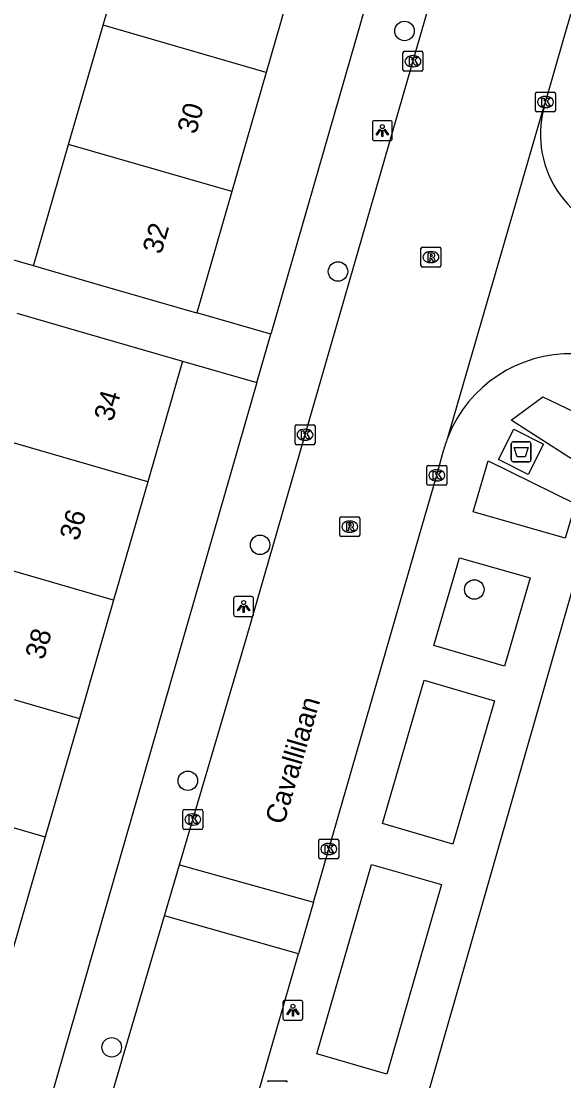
# Model space of a CAD drawing. Extents: x 159822 to 160765, y 380693 to 381634.
# Drawn here: x 160405.7 to 160432.9, y 381176.6 to 381229.8 of the extents above; entities that cross this region are included whole.
import ezdxf

# ---------------------------------------------------------------- set-up
doc = ezdxf.new("R2010")
doc.units = 0
for name, color, linetype in [('IMGEO_Afval_apart_plaats', 7, 'Continuous'), ('IMGEO_Boom', 7, 'Continuous'), ('IMGEO_Brandkraan', 7, 'Continuous'), ('IMGEO_Kolk', 7, 'Continuous'), ('IMGEO_Lichtpunt', 7, 'Continuous'), ('IMGEO_Openbare_ruimte_label', 7, 'Continuous'), ('IMGEO_Pand', 7, 'Continuous'), ('IMGEO_Pand_nummerreeks', 7, 'Continuous'), ('IMGEO_Rijbaan_lokaal_open', 7, 'Continuous'), ('IMGEO_Rioolput', 7, 'Continuous'), ('IMGEO_Voetpad_gesloten', 7, 'Continuous'), ('IMGEO_Voetpad_open', 7, 'Continuous')]:
    doc.layers.add(name, color=color, linetype=linetype)

msp = doc.modelspace()

# ---------------------------------------------------------------- linework, layer by layer
at = {"layer": 'IMGEO_Afval_apart_plaats'}
for p, q in [((160430.31, 381207.756), (160430.31, 381208.556)), ((160430.31, 381208.556), (160430.31, 381207.756)), ((160430.41, 381208.656), (160431.2, 381208.656)), ((160431.2, 381208.656), (160430.41, 381208.656)), ((160431.3, 381208.556), (160431.3, 381207.756)), ((160431.3, 381207.756), (160431.3, 381208.556)), ((160431.2, 381207.656), (160430.41, 381207.656)), ((160430.41, 381207.656), (160431.2, 381207.656))]:
    msp.add_line(p, q, dxfattribs=at)
msp.add_lwpolyline([(160430.453, 381208.37), (160431.157, 381208.37), (160431.008, 381207.9), (160430.602, 381207.9), (160430.453, 381208.37)], dxfattribs=at)
for centre, start, end in [((160430.41, 381208.556), 90, 180), ((160430.41, 381208.556), 90, 180), ((160431.2, 381208.556), 0, 90), ((160431.2, 381208.556), 360, 90), ((160430.41, 381207.756), 180, 270), ((160430.41, 381207.756), 180, 270), ((160431.2, 381207.756), 270, 0), ((160431.2, 381207.756), 270, 0)]:
    msp.add_arc(centre, 0.1, start, end, dxfattribs=at)
at = {"layer": 'IMGEO_Boom'}
for centre in [(160424.957, 381229.276), (160421.624, 381217.206), (160417.717, 381203.486), (160428.46, 381201.244), (160414.092, 381191.645), (160410.275, 381178.268)]:
    msp.add_circle(centre, 0.489, dxfattribs=at)
at = {"layer": 'IMGEO_Brandkraan'}
msp.add_line((160418.157, 381176.587), (160419.009, 381176.587), dxfattribs=at)
msp.add_lwpolyline([(160418.157, 381176.587), (160419.009, 381176.587)], dxfattribs=at)
for centre, start, end in [((160418.159, 381176.511), 91.552, 178.448), ((160418.159, 381176.511), 91.552, 178.448), ((160419.007, 381176.511), 1.552, 88.448), ((160419.007, 381176.511), 1.552, 88.448)]:
    msp.add_arc(centre, 0.0765, start, end, dxfattribs=at)
at = {"layer": 'IMGEO_Kolk'}
for p, q in [((160424.882, 381227.331), (160424.882, 381228.183)), ((160424.957, 381228.257), (160425.809, 381228.257)), ((160425.37, 381228.037), (160425.395, 381228.037)), ((160425.883, 381228.183), (160425.883, 381227.331)), ((160425.393, 381227.477), (160425.368, 381227.477)), ((160425.809, 381227.257), (160424.957, 381227.257)), ((160431.527, 381225.284), (160431.527, 381226.136)), ((160431.602, 381226.21), (160432.454, 381226.21)), ((160432.015, 381225.99), (160432.04, 381225.99)), ((160432.528, 381226.136), (160432.528, 381225.284)), ((160432.038, 381225.43), (160432.013, 381225.43)), ((160432.454, 381225.21), (160431.602, 381225.21)), ((160419.469, 381208.585), (160419.469, 381209.437)), ((160419.544, 381209.511), (160420.396, 381209.511)), ((160419.957, 381209.291), (160419.982, 381209.291)), ((160420.47, 381209.437), (160420.47, 381208.585)), ((160420.396, 381208.511), (160419.544, 381208.511)), ((160419.98, 381208.731), (160419.955, 381208.731)), ((160426.08, 381206.549), (160426.08, 381207.401)), ((160426.155, 381207.475), (160427.007, 381207.475)), ((160426.568, 381207.255), (160426.593, 381207.255)), ((160427.081, 381207.401), (160427.081, 381206.549)), ((160426.591, 381206.695), (160426.566, 381206.695)), ((160427.007, 381206.475), (160426.155, 381206.475)), ((160413.841, 381189.276), (160413.841, 381190.128)), ((160413.916, 381190.202), (160414.768, 381190.202)), ((160414.842, 381190.128), (160414.842, 381189.276)), ((160414.329, 381189.982), (160414.354, 381189.982)), ((160414.768, 381189.202), (160413.916, 381189.202)), ((160414.352, 381189.422), (160414.327, 381189.422)), ((160420.659, 381187.795), (160420.659, 381188.647)), ((160420.734, 381188.721), (160421.586, 381188.721)), ((160421.66, 381188.647), (160421.66, 381187.795)), ((160421.147, 381188.501), (160421.172, 381188.501)), ((160421.586, 381187.721), (160420.734, 381187.721)), ((160421.17, 381187.941), (160421.145, 381187.941))]:
    msp.add_line(p, q, dxfattribs=at)
for points in [[(160424.882, 381227.331), (160424.882, 381228.183)], [(160424.957, 381228.257), (160425.809, 381228.257)], [(160425.203, 381227.957), (160425.326, 381227.957), (160425.326, 381227.806), (160425.456, 381227.957), (160425.62, 381227.957), (160425.474, 381227.806), (160425.627, 381227.557), (160425.475, 381227.557), (160425.39, 381227.721), (160425.326, 381227.654), (160425.326, 381227.557), (160425.203, 381227.557), (160425.203, 381227.957)], [(160425.883, 381228.183), (160425.883, 381227.331)], [(160425.809, 381227.257), (160424.957, 381227.257)], [(160431.527, 381225.284), (160431.527, 381226.136)], [(160431.602, 381226.21), (160432.454, 381226.21)], [(160431.848, 381225.91), (160431.971, 381225.91), (160431.971, 381225.759), (160432.101, 381225.91), (160432.265, 381225.91), (160432.119, 381225.759), (160432.272, 381225.51), (160432.12, 381225.51), (160432.035, 381225.674), (160431.971, 381225.607), (160431.971, 381225.51), (160431.848, 381225.51), (160431.848, 381225.91)], [(160432.528, 381226.136), (160432.528, 381225.284)], [(160432.454, 381225.21), (160431.602, 381225.21)], [(160419.469, 381208.585), (160419.469, 381209.437)], [(160419.544, 381209.511), (160420.396, 381209.511)], [(160420.47, 381209.437), (160420.47, 381208.585)], [(160419.79, 381209.211), (160419.913, 381209.211), (160419.913, 381209.06), (160420.043, 381209.211), (160420.207, 381209.211), (160420.061, 381209.06), (160420.214, 381208.811), (160420.062, 381208.811), (160419.977, 381208.975), (160419.913, 381208.908), (160419.913, 381208.811), (160419.79, 381208.811), (160419.79, 381209.211)], [(160420.396, 381208.511), (160419.544, 381208.511)], [(160426.08, 381206.549), (160426.08, 381207.401)], [(160426.155, 381207.475), (160427.007, 381207.475)], [(160426.401, 381207.175), (160426.524, 381207.175), (160426.524, 381207.024), (160426.654, 381207.175), (160426.818, 381207.175), (160426.672, 381207.024), (160426.825, 381206.775), (160426.673, 381206.775), (160426.588, 381206.939), (160426.524, 381206.872), (160426.524, 381206.775), (160426.401, 381206.775), (160426.401, 381207.175)], [(160427.081, 381207.401), (160427.081, 381206.549)], [(160427.007, 381206.475), (160426.155, 381206.475)], [(160413.841, 381189.276), (160413.841, 381190.128)], [(160413.916, 381190.202), (160414.768, 381190.202)], [(160414.842, 381190.128), (160414.842, 381189.276)], [(160414.162, 381189.902), (160414.285, 381189.902), (160414.285, 381189.751), (160414.415, 381189.902), (160414.579, 381189.902), (160414.433, 381189.751), (160414.586, 381189.502), (160414.434, 381189.502), (160414.349, 381189.666), (160414.285, 381189.599), (160414.285, 381189.502), (160414.162, 381189.502), (160414.162, 381189.902)], [(160414.768, 381189.202), (160413.916, 381189.202)], [(160420.659, 381187.795), (160420.659, 381188.647)], [(160420.734, 381188.721), (160421.586, 381188.721)], [(160421.66, 381188.647), (160421.66, 381187.795)], [(160420.98, 381188.421), (160421.103, 381188.421), (160421.103, 381188.27), (160421.233, 381188.421), (160421.397, 381188.421), (160421.251, 381188.27), (160421.404, 381188.021), (160421.252, 381188.021), (160421.167, 381188.185), (160421.103, 381188.118), (160421.103, 381188.021), (160420.98, 381188.021), (160420.98, 381188.421)], [(160421.586, 381187.721), (160420.734, 381187.721)]]:
    msp.add_lwpolyline(points, dxfattribs=at)
for centre, start, end in [((160424.959, 381228.181), 91.552, 178.448), ((160424.959, 381228.181), 91.552, 178.448), ((160425.807, 381228.181), 1.552, 88.448), ((160425.807, 381228.181), 1.552, 88.448), ((160424.959, 381227.333), 181.552, 268.448), ((160424.959, 381227.333), 181.552, 268.448), ((160425.807, 381227.333), 271.552, 358.448), ((160425.807, 381227.333), 271.552, 358.448), ((160431.604, 381226.134), 91.552, 178.448), ((160431.604, 381226.134), 91.552, 178.448), ((160432.452, 381226.134), 1.552, 88.448), ((160432.452, 381226.134), 1.552, 88.448), ((160431.604, 381225.286), 181.552, 268.448), ((160431.604, 381225.286), 181.552, 268.448), ((160432.452, 381225.286), 271.552, 358.448), ((160432.452, 381225.286), 271.552, 358.448), ((160419.546, 381209.435), 91.552, 178.448), ((160419.546, 381209.435), 91.552, 178.448), ((160420.394, 381209.435), 1.552, 88.448), ((160420.394, 381209.435), 1.552, 88.448), ((160419.546, 381208.587), 181.552, 268.448), ((160419.546, 381208.587), 181.552, 268.448), ((160420.394, 381208.587), 271.552, 358.448), ((160420.394, 381208.587), 271.552, 358.448), ((160426.157, 381207.399), 91.552, 178.448), ((160426.157, 381207.399), 91.552, 178.448), ((160427.005, 381207.399), 1.552, 88.448), ((160427.005, 381207.399), 1.552, 88.448), ((160426.157, 381206.551), 181.552, 268.448), ((160426.157, 381206.551), 181.552, 268.448), ((160427.005, 381206.551), 271.552, 358.448), ((160427.005, 381206.551), 271.552, 358.448), ((160413.918, 381190.126), 91.552, 178.448), ((160413.918, 381190.126), 91.552, 178.448), ((160414.766, 381190.126), 1.552, 88.448), ((160414.766, 381190.126), 1.552, 88.448), ((160413.918, 381189.278), 181.552, 268.448), ((160413.918, 381189.278), 181.552, 268.448), ((160414.766, 381189.278), 271.552, 358.448), ((160414.766, 381189.278), 271.552, 358.448), ((160420.736, 381188.645), 91.552, 178.448), ((160420.736, 381188.645), 91.552, 178.448), ((160421.584, 381188.645), 1.552, 88.448), ((160421.584, 381188.645), 1.552, 88.448), ((160420.736, 381187.797), 181.552, 268.448), ((160420.736, 381187.797), 181.552, 268.448), ((160421.584, 381187.797), 271.552, 358.448), ((160421.584, 381187.797), 271.552, 358.448)]:
    msp.add_arc(centre, 0.0765, start, end, dxfattribs=at)
for centre, major_axis, ratio, start_param, end_param in [((160425.369, 381227.757), (-0.387, 0.002), 0.722429, 4.712389, 7.853982), ((160425.394, 381227.757), (-0.39, 0.002), 0.717154, 1.570796, 4.712389), ((160432.014, 381225.71), (-0.387, 0.002), 0.722429, 4.712389, 7.853982), ((160432.039, 381225.71), (-0.39, 0.002), 0.717154, 1.570796, 4.712389), ((160419.956, 381209.011), (-0.387, 0.002), 0.722429, 4.712389, 7.853982), ((160419.981, 381209.011), (-0.39, 0.002), 0.717154, 1.570796, 4.712389), ((160426.567, 381206.975), (-0.387, 0.002), 0.722429, 4.712389, 7.853982), ((160426.592, 381206.975), (-0.39, 0.002), 0.717154, 1.570796, 4.712389), ((160414.328, 381189.702), (-0.387, 0.002), 0.722429, 4.712389, 7.853982), ((160414.353, 381189.702), (-0.39, 0.002), 0.717154, 1.570796, 4.712389), ((160421.146, 381188.221), (-0.387, 0.002), 0.722429, 4.712389, 7.853982), ((160421.171, 381188.221), (-0.39, 0.002), 0.717154, 1.570796, 4.712389)]:
    msp.add_ellipse(centre, major_axis=major_axis, ratio=ratio, start_param=start_param, end_param=end_param, dxfattribs=at)
at = {"layer": 'IMGEO_Lichtpunt'}
for p, q in [((160424.25, 381224.774), (160423.442, 381224.774)), ((160424.25, 381224.774), (160423.442, 381224.774)), ((160423.348, 381224.679), (160423.348, 381223.872)), ((160423.348, 381224.679), (160423.348, 381223.872)), ((160424.344, 381223.872), (160424.344, 381224.679)), ((160424.344, 381223.872), (160424.344, 381224.679)), ((160423.442, 381223.778), (160424.25, 381223.778)), ((160423.442, 381223.778), (160424.25, 381223.778)), ((160416.39, 381200.793), (160416.39, 381199.986)), ((160416.39, 381200.793), (160416.39, 381199.986)), ((160417.292, 381200.888), (160416.484, 381200.888)), ((160417.292, 381200.888), (160416.484, 381200.888)), ((160417.386, 381199.986), (160417.386, 381200.793)), ((160417.386, 381199.986), (160417.386, 381200.793)), ((160416.484, 381199.892), (160417.292, 381199.892)), ((160416.484, 381199.892), (160417.292, 381199.892)), ((160419.764, 381180.625), (160418.956, 381180.625)), ((160419.764, 381180.625), (160418.956, 381180.625)), ((160418.862, 381180.53), (160418.862, 381179.723)), ((160418.862, 381180.53), (160418.862, 381179.723)), ((160419.858, 381179.723), (160419.858, 381180.53)), ((160419.858, 381179.723), (160419.858, 381180.53)), ((160418.956, 381179.629), (160419.764, 381179.629)), ((160418.956, 381179.629), (160419.764, 381179.629))]:
    msp.add_line(p, q, dxfattribs=at)
for points in [[(160423.722, 381224.343), (160423.761, 381224.315), (160423.573, 381224.053), (160423.535, 381224.08), (160423.722, 381224.343)], [(160423.824, 381224.295), (160423.871, 381224.295), (160423.871, 381223.973), (160423.824, 381223.973), (160423.824, 381224.295)], [(160423.934, 381224.315), (160423.972, 381224.342), (160424.159, 381224.08), (160424.12, 381224.052), (160423.934, 381224.315)], [(160416.764, 381200.457), (160416.803, 381200.429), (160416.615, 381200.167), (160416.577, 381200.194), (160416.764, 381200.457)], [(160416.866, 381200.409), (160416.913, 381200.409), (160416.913, 381200.087), (160416.866, 381200.087), (160416.866, 381200.409)], [(160416.976, 381200.429), (160417.014, 381200.456), (160417.201, 381200.194), (160417.162, 381200.166), (160416.976, 381200.429)], [(160419.236, 381180.194), (160419.275, 381180.166), (160419.087, 381179.904), (160419.049, 381179.931), (160419.236, 381180.194)], [(160419.338, 381180.146), (160419.385, 381180.146), (160419.385, 381179.824), (160419.338, 381179.824), (160419.338, 381180.146)], [(160419.448, 381180.166), (160419.486, 381180.193), (160419.673, 381179.931), (160419.634, 381179.903), (160419.448, 381180.166)]]:
    msp.add_lwpolyline(points, dxfattribs=at)
for centre in [(160423.847, 381224.477), (160416.889, 381200.591), (160419.361, 381180.328)]:
    msp.add_circle(centre, 0.0994, dxfattribs=at)
for centre, start, end in [((160423.442, 381224.679), 90, 180), ((160423.442, 381224.679), 90, 180), ((160424.25, 381224.679), 0, 90), ((160424.25, 381224.679), 0, 90), ((160423.442, 381223.872), 180, 270), ((160423.442, 381223.872), 180, 270), ((160424.25, 381223.872), 270, 0), ((160424.25, 381223.872), 270, 360), ((160416.484, 381200.793), 90, 180), ((160416.484, 381200.793), 90, 180), ((160417.292, 381200.793), 0, 90), ((160417.292, 381200.793), 0, 90), ((160416.484, 381199.986), 180, 270), ((160416.484, 381199.986), 180, 270), ((160417.292, 381199.986), 270, 0), ((160417.292, 381199.986), 270, 360), ((160418.956, 381180.53), 90, 180), ((160418.956, 381180.53), 90, 180), ((160419.764, 381180.53), 0, 90), ((160419.764, 381180.53), 0, 90), ((160418.956, 381179.723), 180, 270), ((160418.956, 381179.723), 180, 270), ((160419.764, 381179.723), 270, 0), ((160419.764, 381179.723), 270, 360)]:
    msp.add_arc(centre, 0.0946, start, end, dxfattribs=at)
at = {"layer": 'IMGEO_Pand'}
for points in [[(160409.842, 381229.562), (160411.567, 381235.543)], [(160419.75, 381233.175), (160418.023, 381227.194)], [(160408.115, 381223.579), (160409.842, 381229.562)], [(160418.023, 381227.194), (160409.842, 381229.562)], [(160418.023, 381227.194), (160416.297, 381221.211)], [(160406.359, 381217.491), (160408.115, 381223.579)], [(160416.297, 381221.211), (160408.115, 381223.579)], [(160416.297, 381221.211), (160414.541, 381215.129)], [(160414.541, 381215.129), (160414.537, 381215.115), (160409.734, 381216.501), (160406.359, 381217.491)], [(160405.51, 381215.111), (160409.029, 381214.095), (160413.832, 381212.709)], [(160413.832, 381212.709), (160412.085, 381206.656)], [(160412.085, 381206.656), (160403.763, 381209.057)], [(160423.911, 381168.099), (160433.345, 381201.136), (160437.138, 381200.053), (160437.464, 381201.195), (160437.252, 381201.413), (160437.307, 381201.818), (160437.934, 381201.555), (160442.333, 381204.902), (160442.35, 381205.648), (160442.739, 381205.64), (160442.732, 381205.305), (160444.103, 381205.275), (160444.177, 381208.684)], [(160412.085, 381206.656), (160410.37, 381200.717)], [(160410.37, 381200.717), (160402.049, 381203.119)], [(160410.37, 381200.717), (160408.656, 381194.779)], [(160400.334, 381197.18), (160408.656, 381194.779)], [(160408.656, 381194.779), (160406.942, 381188.84)], [(160398.62, 381191.242), (160406.942, 381188.84)], [(160406.942, 381188.84), (160405.228, 381182.901)]]:
    msp.add_lwpolyline(points, dxfattribs=at)
at = {"layer": 'IMGEO_Rijbaan_lokaal_open'}
for points in [[(160413.672, 381187.423), (160417.03, 381198.827), (160430.481, 381245.413)], [(160431.938, 381225.406), (160432.026, 381225.71), (160432.938, 381228.843), (160437.189, 381243.571)], [(160427.147, 381208.922), (160431.938, 381225.406)], [(160420.388, 381185.555), (160425.673, 381203.87), (160426.58, 381206.975), (160426.927, 381208.275)], [(160412.919, 381184.867), (160413.672, 381187.423)], [(160413.672, 381187.423), (160420.388, 381185.555)], [(160420.388, 381185.555), (160419.643, 381182.965)], [(160410.006, 381174.977), (160412.919, 381184.867)], [(160419.643, 381182.965), (160412.919, 381184.867)], [(160415.163, 381167.44), (160419.643, 381182.965)]]:
    msp.add_lwpolyline(points, dxfattribs=at)
for centre, radius, start, end in [((160436.986, 381224.104), 5.213, 165.5334, 266.3494), ((160433.272, 381206.479), 6.594, 88.403, 158.2574), ((160433.629, 381206.357), 6.971, 158.4109, 164.0298)]:
    msp.add_arc(centre, radius, start, end, dxfattribs=at)
at = {"layer": 'IMGEO_Rioolput'}
for p, q in [((160425.785, 381217.502), (160425.785, 381218.354)), ((160425.86, 381218.428), (160426.712, 381218.428)), ((160426.786, 381218.354), (160426.786, 381217.502)), ((160426.273, 381218.208), (160426.298, 381218.208)), ((160426.712, 381217.428), (160425.86, 381217.428)), ((160426.296, 381217.648), (160426.271, 381217.648)), ((160421.713, 381203.972), (160421.713, 381204.824)), ((160421.788, 381204.898), (160422.64, 381204.898)), ((160422.201, 381204.678), (160422.226, 381204.678)), ((160422.714, 381204.824), (160422.714, 381203.972)), ((160422.224, 381204.118), (160422.199, 381204.118)), ((160422.64, 381203.898), (160421.788, 381203.898))]:
    msp.add_line(p, q, dxfattribs=at)
for points in [[(160425.785, 381217.502), (160425.785, 381218.354)], [(160425.86, 381218.428), (160426.712, 381218.428)], [(160426.786, 381218.354), (160426.786, 381217.502)], [(160426.374, 381218.126), (160426.122, 381218.128), (160426.122, 381217.728)], [(160426.122, 381217.728), (160426.246, 381217.728), (160426.246, 381217.89), (160426.257, 381217.89)], [(160426.3, 381218.047), (160426.246, 381218.047), (160426.246, 381217.966)], [(160426.246, 381217.966), (160426.298, 381217.966)], [(160426.304, 381217.861), (160426.375, 381217.728), (160426.515, 381217.728), (160426.45, 381217.854)], [(160426.712, 381217.428), (160425.86, 381217.428)], [(160421.713, 381203.972), (160421.713, 381204.824)], [(160421.788, 381204.898), (160422.64, 381204.898)], [(160422.302, 381204.596), (160422.05, 381204.598), (160422.05, 381204.198)], [(160422.228, 381204.517), (160422.174, 381204.517), (160422.174, 381204.436)], [(160422.714, 381204.824), (160422.714, 381203.972)], [(160422.05, 381204.198), (160422.174, 381204.198), (160422.174, 381204.36), (160422.185, 381204.36)], [(160422.174, 381204.436), (160422.226, 381204.436)], [(160422.232, 381204.331), (160422.303, 381204.198), (160422.443, 381204.198), (160422.378, 381204.324)], [(160422.64, 381203.898), (160421.788, 381203.898)]]:
    msp.add_lwpolyline(points, dxfattribs=at)
for centre, radius, start, end in [((160425.862, 381218.352), 0.0765, 91.552, 178.448), ((160425.862, 381218.352), 0.0765, 91.552, 178.448), ((160426.71, 381218.352), 0.0765, 1.552, 88.448), ((160426.71, 381218.352), 0.0765, 1.552, 88.448), ((160426.256, 381217.837), 0.0533, 26.0293, 88.6989), ((160426.282, 381218.155), 0.19, 274.7715, 282.9687), ((160426.306, 381217.951), 0.0964, 77.0061, 93.1865), ((160426.32, 381218.008), 0.0378, 276.6634, 79.6772), ((160426.373, 381218.016), 0.109, 350.3612, 89.416), ((160426.371, 381218.016), 0.112, 277.5842, 350.9817), ((160426.355, 381217.801), 0.108, 29.5134, 73.7905), ((160425.862, 381217.504), 0.0765, 181.552, 268.448), ((160425.862, 381217.504), 0.0765, 181.552, 268.448), ((160426.71, 381217.504), 0.0765, 271.552, 358.448), ((160426.71, 381217.504), 0.0765, 271.552, 358.448), ((160421.79, 381204.822), 0.0765, 91.552, 178.448), ((160421.79, 381204.822), 0.0765, 91.552, 178.448), ((160422.234, 381204.421), 0.0964, 77.0061, 93.1865), ((160422.248, 381204.478), 0.0378, 276.6634, 79.6772), ((160422.301, 381204.486), 0.109, 350.3612, 89.416), ((160422.638, 381204.822), 0.0765, 1.552, 88.448), ((160422.638, 381204.822), 0.0765, 1.552, 88.448), ((160421.79, 381203.974), 0.0765, 181.552, 268.448), ((160421.79, 381203.974), 0.0765, 181.552, 268.448), ((160422.184, 381204.307), 0.0533, 26.0293, 88.6989), ((160422.21, 381204.625), 0.19, 274.7715, 282.9687), ((160422.299, 381204.486), 0.112, 277.5842, 350.9817), ((160422.283, 381204.271), 0.108, 29.5134, 73.7905), ((160422.638, 381203.974), 0.0765, 271.552, 358.448), ((160422.638, 381203.974), 0.0765, 271.552, 358.448)]:
    msp.add_arc(centre, radius, start, end, dxfattribs=at)
for centre, major_axis, ratio, start_param, end_param in [((160426.272, 381217.928), (-0.387, 0.002), 0.722429, 4.712389, 7.853982), ((160426.297, 381217.928), (-0.39, 0.002), 0.717154, 1.570796, 4.712389), ((160422.2, 381204.398), (-0.387, 0.002), 0.722429, 4.712389, 7.853982), ((160422.225, 381204.398), (-0.39, 0.002), 0.717154, 1.570796, 4.712389)]:
    msp.add_ellipse(centre, major_axis=major_axis, ratio=ratio, start_param=start_param, end_param=end_param, dxfattribs=at)
at = {"layer": 'IMGEO_Voetpad_gesloten'}
msp.add_lwpolyline([(160431.169, 381207.024), (160429.677, 381207.776), (160430.44, 381209.289), (160431.932, 381208.537), (160431.169, 381207.024)], dxfattribs=at)
at = {"layer": 'IMGEO_Voetpad_open'}
for points in [[(160428.648, 381250.177), (160428.597, 381250), (160418.254, 381214.06)], [(160406.359, 381217.491), (160393.491, 381221.203), (160394.744, 381225.589)], [(160418.254, 381214.06), (160414.541, 381215.129)], [(160417.557, 381211.637), (160418.254, 381214.06)], [(160413.832, 381212.709), (160417.557, 381211.637)], [(160417.557, 381211.637), (160407.24, 381175.79)], [(160430.309, 381209.737), (160431.898, 381210.917), (160438.956, 381207.533), (160435.631, 381206.327), (160430.309, 381209.737)], [(160433.013, 381203.829), (160428.403, 381205.145), (160429.151, 381207.7), (160433.534, 381205.544), (160433.013, 381203.829)], [(160429.974, 381197.403), (160426.437, 381198.438), (160427.722, 381202.842), (160431.259, 381201.825), (160429.974, 381197.403)], [(160429.464, 381195.662), (160427.385, 381188.462), (160423.848, 381189.498), (160425.95, 381196.694), (160429.464, 381195.662)], [(160426.809, 381186.441), (160424.072, 381176.919), (160420.565, 381177.939), (160423.299, 381187.451), (160426.809, 381186.441)]]:
    msp.add_lwpolyline(points, dxfattribs=at)

# ---------------------------------------------------------------- texts
at = {"layer": 'IMGEO_Openbare_ruimte_label'}
msp.add_text('Cavallilaan', height=1, rotation=73.6848, dxfattribs=at).set_placement((160418.907, 381189.398))
at = {"layer": 'IMGEO_Pand_nummerreeks'}
for s, rotation, p in [('30', 73.9001, (160414.494, 381224.054)), ('32', 73.9001, (160412.755, 381218.027)), ('34', 73.899, (160410.319, 381209.626)), ('36', 73.899, (160408.594, 381203.649)), ('38', 73.899, (160406.869, 381197.674))]:
    msp.add_text(s, height=1, rotation=rotation, dxfattribs=at).set_placement(p)

doc.saveas('drawing.dxf')
